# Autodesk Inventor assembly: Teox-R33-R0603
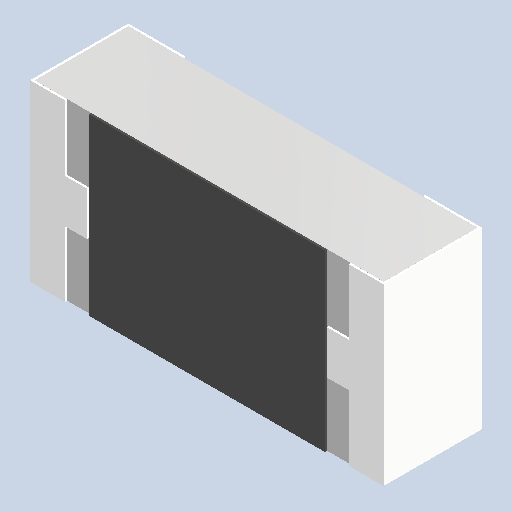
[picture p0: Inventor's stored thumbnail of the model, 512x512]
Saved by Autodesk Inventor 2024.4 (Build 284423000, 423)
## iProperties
Created: 2025-05
Part Number: Teox-R33-R0603
Document SubType Name: Assembly
Designer: AdminForWorker
Title: Teox-R33-R0603
Author: AdminForWorker
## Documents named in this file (2)
- c:\worker\convert-fusion-r02-cosv3\tmp\job-1\2\temp\files\be827049-a7f2-47ea-a815-8d9efd6bfce9\Teox-R33-R0603.iam
- c:\worker\convert-fusion-r02-cosv3\tmp\job-1\2\temp\files\be827049-a7f2-47ea-a815-8d9efd6bfce9\COMPOUND (2).ipt
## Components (1 placed, 1 different names)
1. COMPOUND (2):3
